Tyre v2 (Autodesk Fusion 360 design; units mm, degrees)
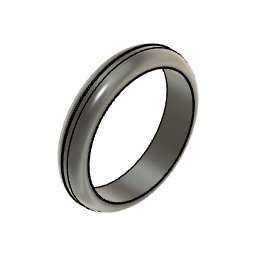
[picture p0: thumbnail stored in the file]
sketch "Sketch1" plane through (0, 0, 0) normal (1, 0, 0) x axis (0, 1, 0)
  circle C1 centre (25, 25) radius 24.2814
extrude "Extrude1" new body sketch "Sketch1" along normal blind 15
fillet "Fillet1" radius 4
shell "Shell1" innerThickness 30
hole "Hole1" HoleDepth 10 HoleDiameter 40 TipAngle 118
fillet "Fillet2" radius 4
pipe "Pipe1" SectionSize 0.5 SectionThickness 0.13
